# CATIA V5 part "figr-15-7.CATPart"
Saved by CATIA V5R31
Part number: Part1
Bounding box of the stored display mesh (mm): x -50 to 50, y -32.5 to 33.5, z -52 to 1
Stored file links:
  D:\PROJECTS\Project 2021\US EDITION\CATIA V5 6R 2021\Resources\Part Files\c15_catia_v5_6r2021_prt\figr-15-7.CATPart
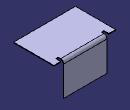
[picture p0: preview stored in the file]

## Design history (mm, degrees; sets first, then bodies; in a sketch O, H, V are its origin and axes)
SheetMetalParameters1: Thickness 1, BendRadius 4, KFactor 0.475772 {= log(min(100,max(20*SheetMetalParameters1.BendRadius,SheetMetalParameters1.Thickness)/SheetMetalParameters1.Thickness))/log(100)/2}, ReliefRadialLength 4, ReliefAxialLength 4, MinimumBendRadius 0
Body1 (main body)
  Sketch1 on xy-plane, origin (0, 0, 0), H (1, 0, 0), V (0, 1, 0)
    line L1 (-50, 32.5) -> (50, 32.5)
    line L2 (50, 32.5) -> (50, -32.5)
    line L3 (50, -32.5) -> (-50, -32.5)
    line L4 (-50, -32.5) -> (-50, 32.5)
    length L1 = 100
    length L2 = 65
    horizontal: L1 H, L3 H
    vertical: L2 V, L4 V
    symmetry: L4 L2 V, L1 L3 H
  Wall1: Thickness 1, Profile Sketch1
  d_NewWallOnEdge1: NewWallOnEdge_Edge edge [face of Wall1 | face of Wall1], NewWallOnEdge_Length 53, NewWallOnEdge_HeightLimitOffset 0, NewWallOnEdge_WidthOffset1 -15, NewWallOnEdge_WidthOffset2 -15, NewWallOnEdge_Angle 90, NewWallOnEdge_BendRadiusValue 4 {= SheetMetalParameters1.BendRadius}, NewWallOnEdge_BendTable SheetMetalParameters1, KFacteur 0.475772 {= log(min(100,max(20*d_NewWallOnEdge1.Radius,SheetMetalParameters1.Thickness)/SheetMetalParameters1.Thickness))/log(100)/2}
